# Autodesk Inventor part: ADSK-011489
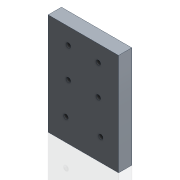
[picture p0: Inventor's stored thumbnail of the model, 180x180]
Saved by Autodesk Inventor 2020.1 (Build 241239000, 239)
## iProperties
Created: 2000-02
Part Number: ADSK-011489
Material: Pearson Aluminium
Document SubType Name: Modeling
Designer: sspink
Density: 2.71 g/cm^3
Appearance: Pearson-Aluminum
Mass: 751.787 g
Surface Area: 405.548 cm^2
Volume: 277.412 cm^3
Control State: 0
Checked Out: False
Master: False
Shininess: 0.0
Length Units: 11269
Angle Units: 11279
Time Units: 11290
Mass Units: 11283
Length Display Precision: 3
Angle Display Precision: 2
Compacted: True
Cutlength: 5.75
Material Desc: FLAT,ALUM,0.75 X 4.00
Dimensions: 101x146x19 mm
Mass: 0,752 kg
Density: 0.0
Volumn: 0.0
Area: 0.0
PropertySet Name: Model Information
Author: sspink
Revision Number: -
Title: ADSK-011489
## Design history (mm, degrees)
node "Solide1"
  node "Extrusion1" dims "d2" = 19, "d3" = 0
  node "Hole1" dims "d4" = 4.917, "d5" = 9.525, "d6" = 6.35, "d7" = 60 deg, "d8" = 17.1, "d9" = 118 deg, "d28" = 12
  node "Hole2" dims "d13" = 6.647, "d14" = 9.525, "d15" = 6.35, "d16" = 60 deg, "d17" = 22.2, "d18" = 118 deg, "d29" = 16
sketch "Sketch1"
  geometry: L1 (-50.5, -73)-(50.5, -73); L2 (50.5, -73)-(50.5, 73); L3 (50.5, 73)-(-50.5, 73); L4 (-50.5, 73)-(-50.5, -73); 3 further points
  constraints: 8 end point, 2 midpoint, 2 parallel, 1 horizontal, 1 horizontal alignment, 1 perpendicular, 1 vertical alignment
  dimensions: "d0" = 146 distance between parallel lines of L1 L3; "d1" = 101 distance between parallel lines of L2 L4
sketch "Sketch2"
  geometry: L1 (-50.5, 73)-(50.5, 73) reference; L2 (-21.5, 49.5)-(21.5, 49.5); L3 (21.5, 49.5)-(21.5, 6.5); L4 (21.5, 6.5)-(-21.5, 6.5); L5 (-21.5, 6.5)-(-21.5, 49.5); 4 further points
  constraints: 8 end point, 2 horizontal alignment, 2 midpoint, 2 parallel, 2 vertical alignment, 1 horizontal, 1 perpendicular
  dimensions: "d25" = 43 distance of L3.end L4.end; "d26" = 43 distance of L4.end L2.start (= d25); "d27" = 23.5 distance between parallel lines of L1 L2
sketch "Sketch3"
  geometry: L1 (50.5, -73)-(-50.5, -73) reference; L2 (-50.5, 73)-(50.5, 73) reference; L3 (0, -73)-(0, 73); 2 further points
  constraints: 2 end point, 2 midpoint, 1 horizontal alignment
  dimensions: "d10" = 50 distance of point (25, -41) point (-25, -41); "d11" = 25 distance from line of L3 point (25, -41) (= 0.5 x d10); "d12" = 32 distance from line of point (-25, -41) L1
node "Corps solides"
node "Corps surfaciques"
